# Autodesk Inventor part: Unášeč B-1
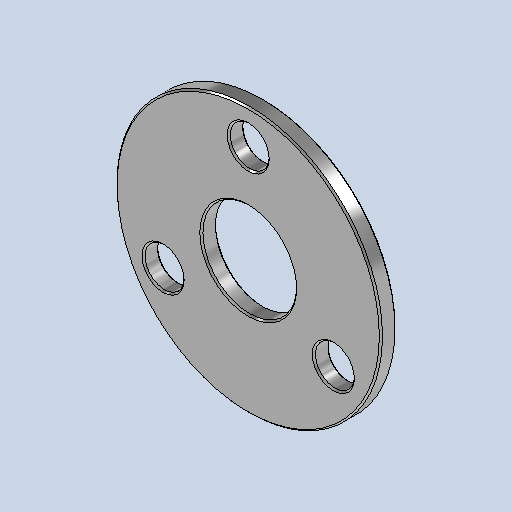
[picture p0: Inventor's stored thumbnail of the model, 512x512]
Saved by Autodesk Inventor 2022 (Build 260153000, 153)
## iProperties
Created: 2025-05
Part Number: Unášeč B-1
Material: Všeobecné
Document SubType Name: Modeling
Designer: jbart
Density: 1 g/cm^3
Appearance: Broušená
Mass: 1464.12 g
Surface Area: 1810.52 cm^2
Volume: 1464.12 cm^3
Author: jbart
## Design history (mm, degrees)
sketch "Náčrt1"
  geometry: L1 (0, 126)-(109.119, -63); L2 (109.119, -63)-(-109.119, -63); L3 (-109.119, -63)-(0, 126); L4 (0, 126)-(0, 0); L5 (0, 0)-(109.119, -63); L6 (0, 0)-(-109.119, -63); C1 r 25 at (0, 126); C2 r 25 at (-109.119, -63); C3 r 25 at (109.119, -63); C4 r 170 at (0, 0); C5 r 60 at (0, 0); 1 further point
  constraints: 12 end point, 6 coincident, 5 centre point, 1 vertical, 7 other
  dimensions: "d0" = 126 distance of L4.end L1.end; "d1" = 50 diameter of C1; "d2" = 50 diameter of C2; "d3" = 50 diameter of C3; "d4" = 340 diameter of C4; "d5" = 120 diameter of C5
extrude "Vysunutí1" new body sketch "Náčrt1" distance "d6" = 20; taper "d7" = 0 deg
chamfer "Zkosení1" distance "d8" = 2; stored, may be unused: second distance "d9" = 2, angle "d10" = 45 deg
node "Těleso1"
